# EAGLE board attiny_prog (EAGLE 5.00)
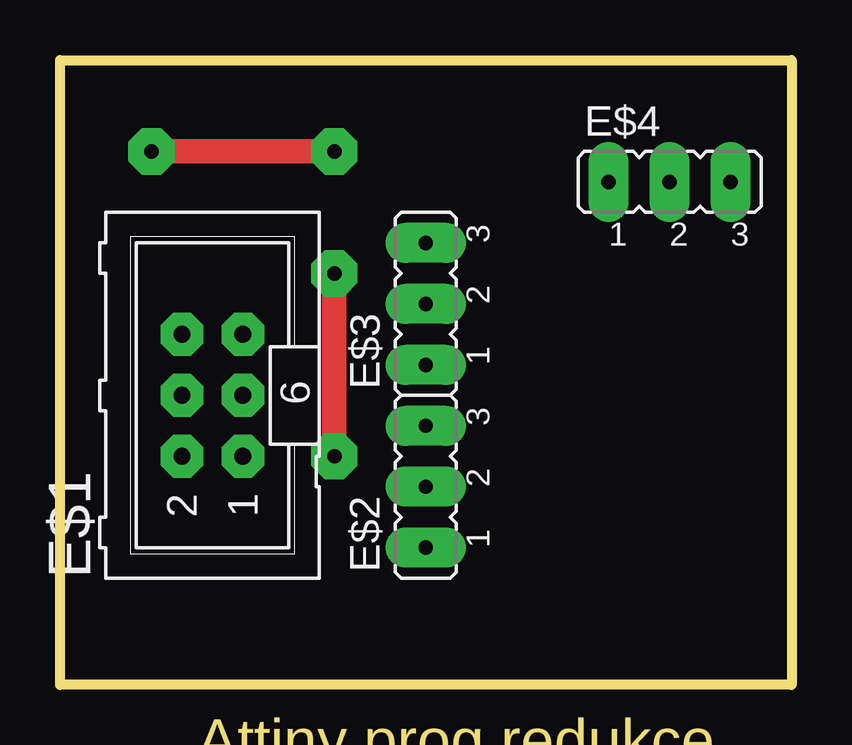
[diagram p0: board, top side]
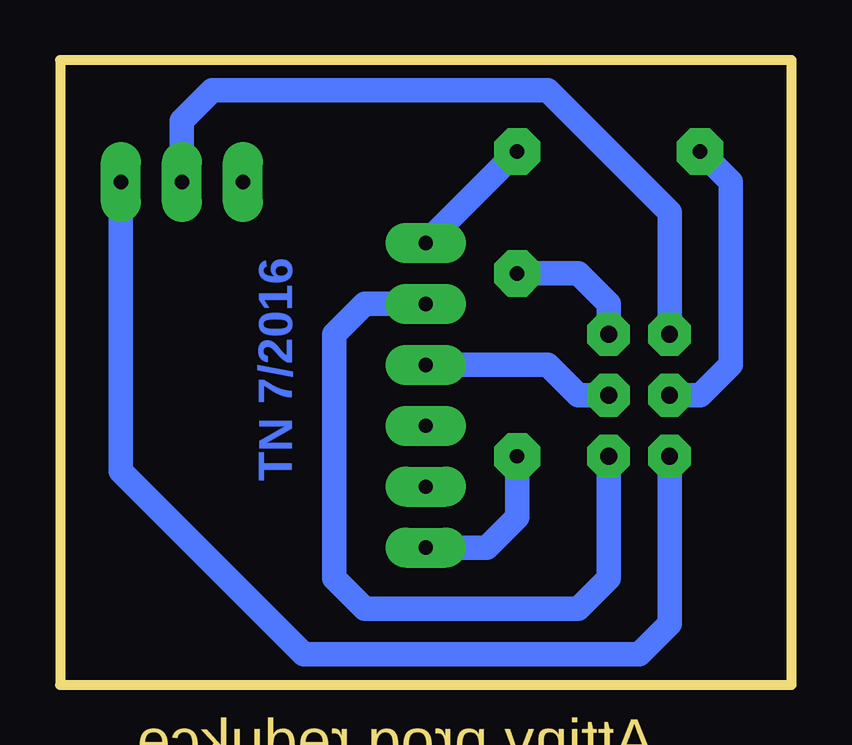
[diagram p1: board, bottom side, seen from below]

Size 30.48 x 26.04 mm. Coordinates in mm from the lower left corner, seen from the top.
Outline: 0,26.04 30.48,26.04 30.48,0 0,0 0,26.04
Copper layers (1*16): Top 0.035mm / dielectric 1.5mm / Bottom 0.035mm
Design rules "default": minimum track width 10mil, minimum drill 24mil, track to track 8mil, track to pad 8mil, pad to pad 8mil, via to via 8mil, smd to smd 8mil, copper to edge 40mil, drill to drill 8mil, minimum pad ring 10mil, minimum via ring 8mil, stop-mask expansion 4mil, vias tented up to drill 0mil, thermal gap 10mil

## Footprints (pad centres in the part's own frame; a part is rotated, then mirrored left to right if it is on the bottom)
ML6 = drill 0.7 pad 1.778 octagon: 1 -2.54,-1.27; 2 -2.54,1.27; 3 0,-1.27; 4 0,1.27; 5 2.54,-1.27; 6 2.54,1.27
JP2Y = drill 0.6 pad 1.676 long: 1 -2.54,0; 2 0,0; 3 2.54,0

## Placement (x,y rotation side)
E$1  [ML6]  6.35,12.07 90 top
E$2  [JP2Y]  15.24,8.26 90 top
E$3  [JP2Y]  15.24,15.88 90 top
E$4  [JP2Y]  25.4,20.95 0 top

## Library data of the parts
E$1-E$4 = 11moje

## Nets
S$1: E$1.1 E$3.2
S$2: E$1.3 E$3.1
S$3: E$1.5 E$2.1
S$4: E$1.2 E$4.3
S$5: E$1.4 E$3.3
S$6: E$1.6 E$4.2

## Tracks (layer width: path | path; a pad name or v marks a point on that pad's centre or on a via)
S$1
  Bottom 1.016: E$3.2 17.78,15.88 19.05,14.61 19.05,4.45 17.78,3.18 8.89,3.18 7.62,4.45 E$1.1
S$2
  Bottom 1.016: E$1.3 8.89,12.07 10.16,13.34 E$3.1
S$3  (via drill 0.6 pad 1.93)
  Top 1.016: v11.43,17.15 v11.43,9.52
  Bottom 1.016: E$1.5 7.62,15.88 8.89,17.15 v11.43,17.15 | v11.43,9.52 11.43,6.98 12.7,5.72 E$2.1
S$4
  Bottom 1.016: E$1.2 5.08,2.54 6.35,1.27 20.32,1.27 27.94,8.89 E$4.3
S$5  (via drill 0.6 pad 1.93)
  Top 1.016: v3.81,22.23 v11.43,22.23
  Bottom 1.016: E$1.4 3.81,12.07 2.54,13.34 2.54,20.95 v3.81,22.23 | v11.43,22.23 E$3.3
S$6
  Bottom 1.016: E$4.2 25.4,23.49 24.13,24.77 10.16,24.77 5.08,19.69 E$1.6

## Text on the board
Bottom: TN 7/2016
Dimension: Attiny prog redukce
